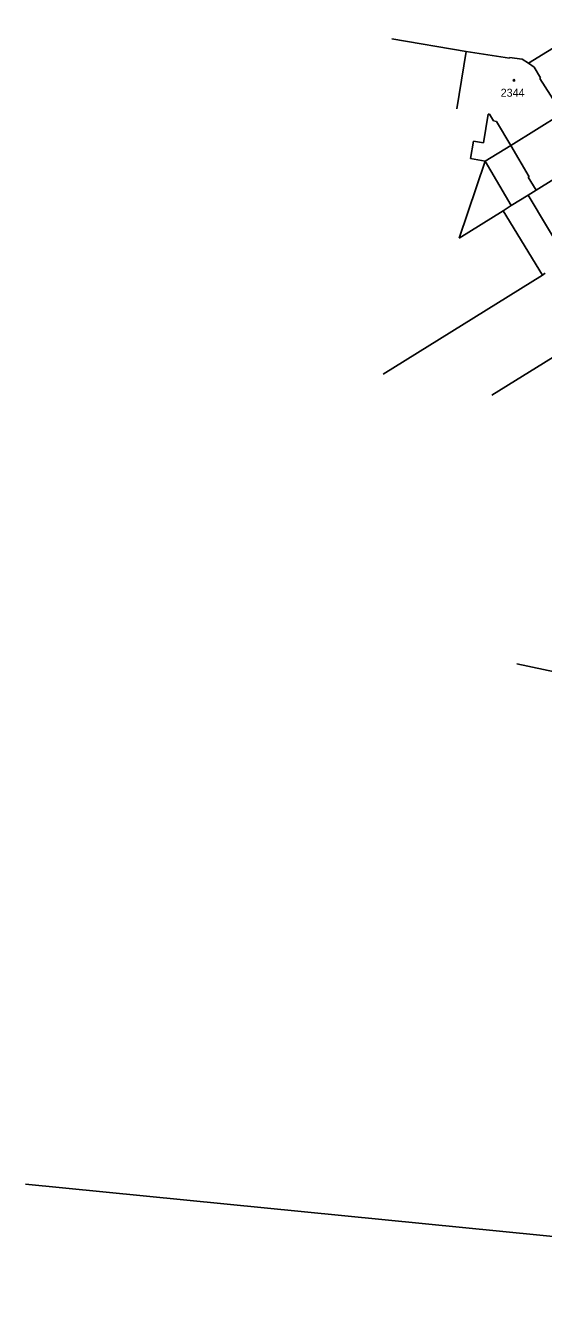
# Model space of a CAD drawing. Extents: x -735092 to -733385, y -1122435 to -1118992.
# Drawn here: x -734978.3 to -734868.2, y -1120128.4 to -1119858.7 of the extents above; entities that cross this region are included whole.
import ezdxf

# ---------------------------------------------------------------- set-up
doc = ezdxf.new("R2010")
doc.units = 0
for name, color, linetype in [('Vrstva 1', 7, 'Continuous'), ('Vrstva 19', 7, 'Continuous'), ('Vrstva 25', 7, 'Continuous'), ('Vrstva 4', 7, 'Continuous')]:
    doc.layers.add(name, color=color, linetype=linetype)

msp = doc.modelspace()

# ---------------------------------------------------------------- linework, layer by layer
at = {"layer": 'Vrstva 1'}
for points in [[(-734871.46, -1119866.75), (-734858.44, -1119858.7)], [(-734900.45, -1119861.53), (-734884.71, -1119864.22)], [(-734886.69, -1119876.4), (-734884.71, -1119864.22)], [(-734884.71, -1119864.22), (-734875.51, -1119865.66)], [(-734875.51, -1119865.66), (-734875.49, -1119865.51)], [(-734875.49, -1119865.51), (-734872.76, -1119865.89)], [(-734872.76, -1119865.89), (-734871.46, -1119866.75)], [(-734871.46, -1119866.75), (-734870.23, -1119867.56)], [(-734870.23, -1119867.56), (-734868.91, -1119869.87)], [(-734869.04, -1119869.95), (-734868.91, -1119869.87)], [(-734869.04, -1119869.95), (-734864.5, -1119877.08)], [(-734875.16, -1119884.23), (-734864.29, -1119877.41)], [(-734880.66, -1119887.53), (-734875.16, -1119884.23)], [(-734886.18, -1119903.88), (-734880.66, -1119887.53)], [(-734883.77, -1119887.01), (-734880.66, -1119887.53)], [(-734880.66, -1119887.53), (-734875.12, -1119896.99)], [(-734869.79, -1119893.68), (-734858.58, -1119886.7)], [(-734875.12, -1119896.99), (-734871.49, -1119894.74)], [(-734871.49, -1119894.74), (-734869.79, -1119893.68)], [(-734886.18, -1119903.88), (-734876.84, -1119898.07)], [(-734876.84, -1119898.07), (-734875.12, -1119896.99)], [(-734876.84, -1119898.07), (-734868.49, -1119911.74)], [(-734902.3, -1119932.83), (-734868.49, -1119911.74)], [(-734868.49, -1119911.74), (-734867.88, -1119911.36)], [(-734879.25, -1119937.27), (-734864.74, -1119928.29)], [(-734873.93, -1119994.37), (-734828.6, -1120003.98)], [(-734978.31, -1120104.89), (-734741.96, -1120128.37)]]:
    msp.add_lwpolyline(points, dxfattribs=at)
at = {"layer": 'Vrstva 25'}
msp.add_circle((-734874.54, -1119870.36), 0.175, dxfattribs=at)
at = {"layer": 'Vrstva 4'}
for points in [[(-734881.01, -1119883.68), (-734879.98, -1119877.55)], [(-734879.98, -1119877.55), (-734879.74, -1119877.59)], [(-734879.74, -1119877.59), (-734878.89, -1119878.97)], [(-734878.89, -1119878.97), (-734878.21, -1119879.15)], [(-734878.21, -1119879.15), (-734875.16, -1119884.23)], [(-734883.77, -1119887.01), (-734883.15, -1119883.32)], [(-734883.15, -1119883.32), (-734881.01, -1119883.68)], [(-734875.16, -1119884.23), (-734871.33, -1119890.89)], [(-734871.48, -1119890.98), (-734871.33, -1119890.89)], [(-734871.48, -1119890.98), (-734869.79, -1119893.68)], [(-734871.49, -1119894.74), (-734863.32, -1119908.51)]]:
    msp.add_lwpolyline(points, dxfattribs=at)

# ---------------------------------------------------------------- texts
at = {"layer": 'Vrstva 19'}
msp.add_text('2344', height=1.7, dxfattribs=at).set_placement((-734877.35, -1119873.86))

doc.saveas('drawing.dxf')
